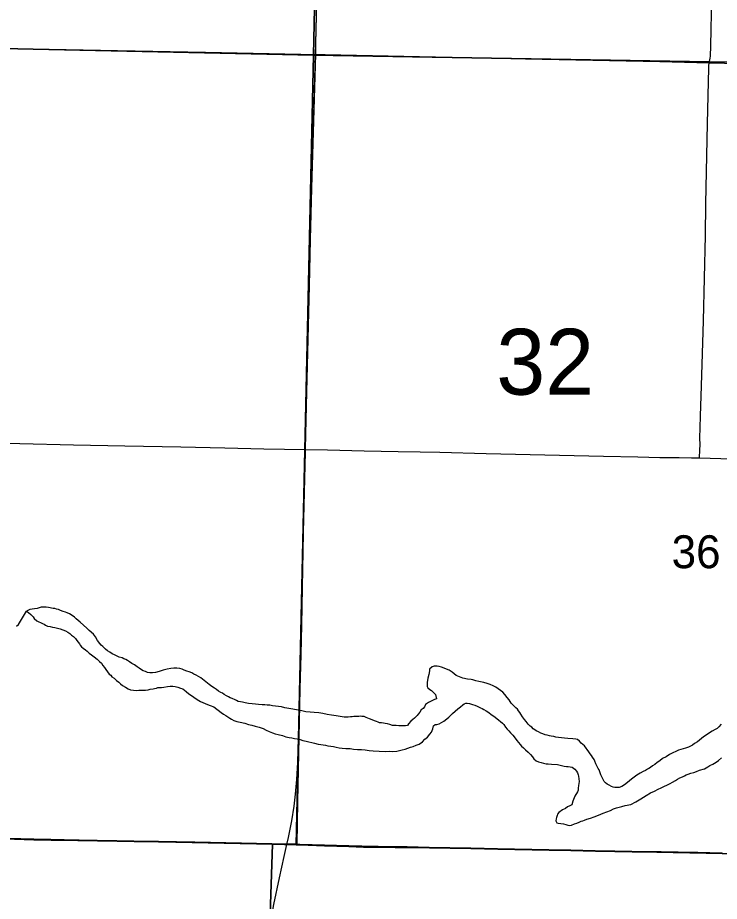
# Model space of a CAD drawing. Extents: x 2.4 to 73.1, y 4.5 to 25.6.
# Drawn here: x 32.789 to 33.235, y 18.547 to 19.109 of the extents above; entities that cross this region are included whole.
import ezdxf

# ---------------------------------------------------------------- set-up
doc = ezdxf.new("R2010")
doc.units = 0
for name, color, linetype in [('GM_X_County_Road', 7, 'Continuous'), ('GM_X_Interchange_Ramps', 7, 'Continuous'), ('GM_X_Major_River', 7, 'Continuous'), ('GM_X_Minor_River', 7, 'Continuous'), ('GM_X_Section', 7, 'Continuous'), ('GM_X_Section_Text', 7, 'Continuous'), ('GM_X_State_Route', 7, 'Continuous'), ('GM_X_Township', 7, 'Continuous'), ('GM_X_Township_Road', 7, 'Continuous')]:
    doc.layers.add(name, color=color, linetype=linetype)

msp = doc.modelspace()

# ---------------------------------------------------------------- linework, layer by layer
at = {"layer": 'GM_X_County_Road'}
for points in [[(33.22907, 19.08006), (33.22948, 19.08189), (33.22967, 19.083), (33.22979, 19.08426), (33.23011, 19.09084), (33.2307, 19.12192)], [(32.47285, 19.09527), (32.47336, 19.09525), (32.51999, 19.09427), (32.53863, 19.09381), (32.55418, 19.09358), (32.63345, 19.09215), (32.70029, 19.09086), (32.72671, 19.09034), (32.74381, 19.0901), (32.77334, 19.0895), (32.78732, 19.08909), (32.8526, 19.08782), (32.90856, 19.08678), (32.96917, 19.08549), (32.97862, 19.08536)], [(32.97862, 19.08536), (32.98472, 19.08527), (33.07486, 19.0834), (33.09351, 19.08306), (33.11215, 19.0826), (33.19765, 19.08101), (33.22907, 19.08006)]]:
    msp.add_lwpolyline(points, dxfattribs=at)
at = {"layer": 'GM_X_Interchange_Ramps'}
msp.add_lwpolyline([(33.23721, 18.57757), (33.22171, 18.578), (33.20931, 18.57828), (33.19844, 18.5785), (33.17982, 18.57874), (33.16895, 18.57888), (33.15653, 18.57913), (33.141, 18.57957), (33.12702, 18.57981), (33.0944, 18.58047), (33.07732, 18.58081), (33.05091, 18.58129), (33.03693, 18.58156), (33.02918, 18.5816), (33.01523, 18.58162), (33.00903, 18.58177), (32.99974, 18.58218), (32.98422, 18.58264), (32.96871, 18.58319), (32.96697, 18.58323), (32.96671, 18.58324), (32.96026, 18.58338), (32.93145, 18.584), (32.90193, 18.58465), (32.87863, 18.58509), (32.86309, 18.58529), (32.85222, 18.58553), (32.82737, 18.58591), (32.81028, 18.58621), (32.79941, 18.58646), (32.77456, 18.58717)], dxfattribs=at)
at = {"layer": 'GM_X_Major_River'}
for points in [[(32.94793, 18.6718), (32.94641, 18.67199), (32.9447, 18.672), (32.94242, 18.67219), (32.94033, 18.67239), (32.93824, 18.67258), (32.93596, 18.67278), (32.93387, 18.67317), (32.93216, 18.67355), (32.93082, 18.67375), (32.92949, 18.67413), (32.92835, 18.6747), (32.92741, 18.67509), (32.92551, 18.67604), (32.92437, 18.67642), (32.92323, 18.677), (32.9219, 18.67757), (32.92057, 18.67853), (32.91943, 18.67929), (32.91829, 18.67986), (32.91696, 18.68063), (32.91563, 18.68158), (32.9143, 18.68254), (32.91259, 18.68349), (32.91088, 18.68483), (32.90575, 18.68902), (32.90423, 18.68998), (32.90271, 18.69074), (32.90119, 18.69151), (32.89987, 18.69227), (32.89834, 18.69284), (32.89682, 18.69342), (32.89511, 18.69399), (32.89378, 18.69457), (32.89226, 18.69495), (32.89036, 18.69515), (32.88846, 18.69515), (32.88656, 18.69497), (32.88428, 18.6946), (32.88161, 18.69403), (32.87914, 18.69309), (32.87686, 18.69253), (32.87496, 18.69234), (32.87325, 18.69235), (32.87173, 18.69254), (32.87039, 18.69311), (32.86906, 18.6935), (32.86736, 18.69464), (32.86641, 18.69522), (32.86508, 18.69617), (32.86356, 18.69732), (32.86185, 18.69827), (32.86033, 18.69923), (32.859, 18.70018), (32.85786, 18.70075), (32.85672, 18.70114), (32.85558, 18.70171), (32.85368, 18.70229), (32.85235, 18.70286), (32.85083, 18.70362), (32.84931, 18.70439), (32.84779, 18.70534), (32.84627, 18.7063), (32.84494, 18.70725), (32.84323, 18.70897), (32.84228, 18.70992), (32.84133, 18.71087), (32.83982, 18.71278), (32.83868, 18.71525), (32.83735, 18.71678), (32.83469, 18.71925), (32.83318, 18.72059), (32.829, 18.7244), (32.82767, 18.72555), (32.82634, 18.72669), (32.8252, 18.72765), (32.82387, 18.72879), (32.82216, 18.72974), (32.82064, 18.73051), (32.8195, 18.73089), (32.81798, 18.73128), (32.81646, 18.73185), (32.81514, 18.73242), (32.8138, 18.73281), (32.81285, 18.73319), (32.81171, 18.73319), (32.81076, 18.73339), (32.80981, 18.73358), (32.80867, 18.73377), (32.80734, 18.73397), (32.8062, 18.73397), (32.80525, 18.73397), (32.80411, 18.73398), (32.80278, 18.7336), (32.80164, 18.73322), (32.79992, 18.73304), (32.7984, 18.73266), (32.79688, 18.73248), (32.79479, 18.73153), (32.79593, 18.73058), (32.79745, 18.72924)], [(32.79745, 18.72924), (32.79896, 18.72791), (32.79972, 18.72677), (32.80124, 18.72524), (32.80257, 18.72467), (32.80371, 18.72428), (32.80485, 18.72371), (32.80599, 18.72314), (32.80694, 18.72256), (32.80808, 18.72199), (32.80979, 18.72161), (32.81131, 18.72122), (32.81283, 18.72103), (32.81454, 18.72064), (32.81625, 18.72026), (32.81796, 18.71968), (32.81948, 18.71892), (32.821, 18.71815), (32.82233, 18.7172), (32.82347, 18.71625), (32.82461, 18.71529), (32.82594, 18.71415), (32.8267, 18.71282), (32.82765, 18.71167), (32.82841, 18.71072), (32.82897, 18.70977), (32.82973, 18.70882), (32.83087, 18.70786), (32.8322, 18.70691), (32.83334, 18.70595), (32.83467, 18.70481), (32.83619, 18.70366), (32.8379, 18.70252), (32.8398, 18.70099), (32.84112, 18.69947), (32.84245, 18.69833), (32.8434, 18.69699), (32.84435, 18.69566), (32.8453, 18.69433), (32.84738, 18.69147), (32.84833, 18.69071), (32.84909, 18.68975), (32.85061, 18.6888), (32.85194, 18.68747), (32.85346, 18.68632), (32.8546, 18.68518), (32.85593, 18.68422), (32.85783, 18.68308), (32.85935, 18.68212), (32.86087, 18.68155), (32.86277, 18.68116), (32.86448, 18.68097), (32.86619, 18.68115), (32.86809, 18.68115), (32.87056, 18.68133), (32.87209, 18.68152), (32.87342, 18.68189), (32.87532, 18.68208), (32.87627, 18.68226), (32.87741, 18.68245), (32.87836, 18.68283), (32.8795, 18.68302), (32.88064, 18.68301), (32.88217, 18.6832), (32.88445, 18.68357), (32.88616, 18.68376), (32.88787, 18.68375), (32.88939, 18.68356), (32.8911, 18.68317), (32.89262, 18.6826), (32.89414, 18.68202), (32.89528, 18.68126), (32.89642, 18.68031), (32.89794, 18.67897), (32.89908, 18.67821), (32.90117, 18.67687), (32.90269, 18.67573), (32.9044, 18.67458), (32.90554, 18.67401), (32.90687, 18.67343), (32.90839, 18.67286), (32.90991, 18.67209), (32.91162, 18.67152), (32.9139, 18.67056), (32.91864, 18.66694), (32.91997, 18.66599), (32.92149, 18.66522), (32.92282, 18.66427), (32.92415, 18.6635), (32.9251, 18.66274), (32.92662, 18.66197), (32.92852, 18.6614), (32.93061, 18.66082), (32.93365, 18.66024), (32.93593, 18.65948), (32.93802, 18.6589), (32.9403, 18.65832), (32.94278, 18.65775), (32.94525, 18.65679), (32.94714, 18.65583), (32.94923, 18.65488)], [(33.10176, 18.67515), (33.10043, 18.67668), (33.09911, 18.67858), (33.09778, 18.67992), (33.09322, 18.68316), (33.09151, 18.68393), (33.0898, 18.68488), (33.08771, 18.68546), (33.08562, 18.68603), (33.08258, 18.6868), (33.08049, 18.68719), (33.07878, 18.68776), (33.07764, 18.68796), (33.07536, 18.68816), (33.07232, 18.68892), (33.06814, 18.69065), (33.06548, 18.69274), (33.06358, 18.69389), (33.06187, 18.69466), (33.06035, 18.69523), (33.05883, 18.6958), (33.05731, 18.69619), (33.05598, 18.69657), (33.05503, 18.69658), (33.05408, 18.69658), (33.05275, 18.69601), (33.05122, 18.6945), (33.05103, 18.69355), (33.05064, 18.69127), (33.05007, 18.6888), (33.04968, 18.68614), (33.04968, 18.68481), (33.04968, 18.68367), (33.05006, 18.68272), (33.05139, 18.68176), (33.05234, 18.681), (33.05405, 18.67928), (33.055, 18.67852), (33.05556, 18.67567), (33.05423, 18.67529), (33.05252, 18.67454), (33.05042, 18.6734), (33.04852, 18.67208), (33.04794, 18.67056), (33.04699, 18.66961), (33.04585, 18.66866), (33.0449, 18.66715), (33.04394, 18.66601), (33.04318, 18.66506), (33.04166, 18.66335), (33.04052, 18.6626), (33.03918, 18.66146), (33.03785, 18.65994), (33.03709, 18.65881), (33.03594, 18.65862), (33.03442, 18.65862), (33.03309, 18.65863), (33.03157, 18.65863), (33.02986, 18.65883), (33.02758, 18.65883), (33.02587, 18.65941), (33.02435, 18.65979), (33.02302, 18.65999), (33.02188, 18.66018), (33.02055, 18.66037), (33.01941, 18.66057), (33.01846, 18.66095), (33.01732, 18.66133), (33.01618, 18.66172), (33.01466, 18.66229), (33.01295, 18.66306), (33.01086, 18.66382), (33.00953, 18.6644), (33.00801, 18.66459), (33.00706, 18.66478), (33.0061, 18.6646), (33.00306, 18.66442), (33.00192, 18.66423), (33.00078, 18.66423), (32.99945, 18.66405), (32.99679, 18.66405), (32.99432, 18.66444), (32.99165, 18.66502), (32.9888, 18.66541), (32.98595, 18.66579), (32.98329, 18.66637), (32.98063, 18.66676), (32.97778, 18.66696), (32.97512, 18.66735), (32.97245, 18.66754), (32.96998, 18.66812), (32.96751, 18.66851), (32.96428, 18.66909), (32.96162, 18.66948), (32.95915, 18.67005), (32.95687, 18.67063), (32.95497, 18.67083), (32.95307, 18.67102), (32.95117, 18.67122), (32.94965, 18.6716), (32.94793, 18.6718)], [(33.23655, 18.65956), (33.23521, 18.65785), (33.23407, 18.6569), (33.23293, 18.65615), (33.23102, 18.6552), (33.2255, 18.65161), (33.2215, 18.64839), (33.21979, 18.64725), (33.21846, 18.64631), (33.21579, 18.64498), (33.21389, 18.64442), (33.20952, 18.6431), (33.2078, 18.64235), (33.2059, 18.6414), (33.20381, 18.64027), (33.20171, 18.63894), (33.19924, 18.63781), (33.19771, 18.63629), (33.196, 18.63516), (33.19448, 18.63402), (33.19296, 18.63308), (33.19162, 18.63213), (33.19067, 18.63137), (33.18972, 18.631), (33.18858, 18.63024), (33.18705, 18.62948), (33.18515, 18.62854), (33.18306, 18.62721), (33.17963, 18.62456), (33.17716, 18.62248), (33.17506, 18.62097), (33.17354, 18.62002), (33.17183, 18.61945), (33.16992, 18.61946), (33.16897, 18.61946), (33.16802, 18.61966), (33.16688, 18.62004), (33.16536, 18.6208), (33.16403, 18.62138), (33.16308, 18.62233), (33.16233, 18.62328), (33.16138, 18.62481), (33.16062, 18.62652), (33.16005, 18.62747), (33.15967, 18.62861), (33.15911, 18.63051), (33.15835, 18.63147), (33.15778, 18.6328), (33.15683, 18.63432), (33.15626, 18.63603), (33.15589, 18.63718), (33.15475, 18.6387), (33.15418, 18.63965), (33.15342, 18.64079), (33.15247, 18.64194), (33.14963, 18.64575), (33.14868, 18.6467), (33.14754, 18.64765), (33.14659, 18.6488), (33.14526, 18.64994), (33.14412, 18.65013), (33.14222, 18.65033), (33.13918, 18.65053), (33.1369, 18.65073), (33.135, 18.65092), (33.13309, 18.65112), (33.13157, 18.65131), (33.13024, 18.6517), (33.12853, 18.65189), (33.12739, 18.65227), (33.12606, 18.65266), (33.12473, 18.65285), (33.12321, 18.65343), (33.12188, 18.654), (33.12036, 18.65476), (33.11903, 18.65534), (33.11808, 18.6561), (33.11713, 18.65667), (33.11618, 18.65763), (33.11523, 18.65839), (33.11391, 18.65972), (33.11258, 18.66125), (33.11163, 18.66258), (33.1103, 18.6643), (33.10916, 18.66601), (33.10859, 18.66696), (33.10783, 18.66811), (33.10708, 18.66906), (33.10613, 18.67001), (33.1048, 18.67134), (33.10309, 18.67306), (33.10176, 18.67515)], [(32.94923, 18.65488), (32.95114, 18.65411), (32.95303, 18.65354), (32.95494, 18.65296), (32.9576, 18.65238), (32.95969, 18.65162), (32.96178, 18.65123), (32.96349, 18.65084), (32.9652, 18.65046), (32.96691, 18.65027), (32.96881, 18.64988), (32.97052, 18.6493), (32.97261, 18.64892), (32.97432, 18.64834), (32.97622, 18.64796), (32.97793, 18.64757), (32.98021, 18.647), (32.98192, 18.64661), (32.98344, 18.64642), (32.98497, 18.64622), (32.98649, 18.64584), (32.98839, 18.64564), (32.9901, 18.64545), (32.99181, 18.64506), (32.99371, 18.64468), (32.99561, 18.64429), (32.99789, 18.64409), (33.00074, 18.64409), (33.00283, 18.6437), (33.00531, 18.6435), (33.00778, 18.64349), (33.01025, 18.6433), (33.01272, 18.64291), (33.01519, 18.64271), (33.02299, 18.64231), (33.02546, 18.64249), (33.02774, 18.6423), (33.0304, 18.64248), (33.03211, 18.64286), (33.03383, 18.64323), (33.03573, 18.64379), (33.03725, 18.64436), (33.03896, 18.64493), (33.04067, 18.64549), (33.04258, 18.64625), (33.04448, 18.647), (33.04657, 18.64833), (33.0481, 18.65003), (33.04981, 18.65136), (33.05134, 18.65325), (33.05248, 18.65458), (33.05324, 18.65667), (33.05363, 18.65857), (33.05477, 18.65932), (33.05572, 18.65951), (33.05724, 18.65989), (33.05877, 18.66064), (33.06029, 18.66159), (33.06219, 18.66291), (33.06333, 18.66405), (33.06448, 18.66519), (33.06581, 18.66633), (33.06753, 18.66784), (33.06924, 18.66936), (33.07076, 18.67068), (33.07229, 18.67182), (33.07324, 18.67258), (33.07419, 18.67295), (33.07514, 18.67295), (33.07666, 18.67276), (33.07837, 18.67218), (33.07989, 18.67161), (33.08141, 18.67103), (33.0835, 18.67007), (33.08464, 18.66969), (33.08578, 18.66893), (33.08711, 18.66816), (33.08882, 18.66702), (33.09034, 18.66587), (33.09205, 18.66473), (33.09395, 18.6632), (33.09755, 18.66034), (33.0985, 18.65939), (33.09945, 18.65768), (33.10059, 18.65634), (33.10154, 18.65539), (33.10268, 18.65406), (33.10419, 18.65272), (33.10552, 18.65063), (33.10666, 18.64929), (33.1078, 18.64796), (33.10875, 18.64663), (33.1097, 18.64567), (33.11083, 18.64453), (33.11216, 18.64338), (33.11387, 18.64186), (33.11539, 18.64033), (33.11672, 18.63881), (33.11748, 18.63748), (33.119, 18.63633), (33.12052, 18.63576)], [(33.12052, 18.63576), (33.12223, 18.63518), (33.12356, 18.6348), (33.12527, 18.63441), (33.1266, 18.63441), (33.12869, 18.63421), (33.13249, 18.63401), (33.13515, 18.63343), (33.13686, 18.63286), (33.13819, 18.63267), (33.13933, 18.63266), (33.14067, 18.63247), (33.14181, 18.63228), (33.14351, 18.63094), (33.14465, 18.6298), (33.14522, 18.62865), (33.14579, 18.62751), (33.14598, 18.62656), (33.14635, 18.62314), (33.14616, 18.622), (33.14597, 18.62067), (33.14578, 18.61896), (33.14577, 18.61763), (33.1452, 18.61668), (33.14367, 18.61383), (33.14234, 18.61061), (33.14157, 18.60833), (33.14043, 18.60776), (33.13891, 18.60701), (33.13758, 18.60606), (33.13567, 18.60511), (33.13339, 18.60341), (33.13263, 18.60246), (33.13225, 18.60151), (33.13186, 18.60037), (33.13167, 18.59942), (33.13148, 18.59809), (33.13205, 18.59695), (33.133, 18.59676), (33.13471, 18.59656), (33.13642, 18.59618), (33.13794, 18.59579), (33.13908, 18.59541), (33.14022, 18.59522), (33.14155, 18.5954), (33.14326, 18.59616), (33.14479, 18.59673), (33.14631, 18.59729), (33.14764, 18.59786), (33.14859, 18.59824), (33.14973, 18.59861), (33.15125, 18.59918), (33.15354, 18.59993), (33.15582, 18.60068), (33.15867, 18.60182), (33.16153, 18.60295), (33.164, 18.60389), (33.16629, 18.60484), (33.16819, 18.60578), (33.17009, 18.60634), (33.1718, 18.60691), (33.17351, 18.60729), (33.17561, 18.60785), (33.17922, 18.6086), (33.18227, 18.6103), (33.1855, 18.61219), (33.18893, 18.61427), (33.19178, 18.61597), (33.19426, 18.61711), (33.19654, 18.61824), (33.19845, 18.61919), (33.20415, 18.62183), (33.20568, 18.62278), (33.20758, 18.62391), (33.20891, 18.62467), (33.21044, 18.62561), (33.21196, 18.62618), (33.21329, 18.62675), (33.21443, 18.62731), (33.21576, 18.62788), (33.21728, 18.62845), (33.21919, 18.62882), (33.2209, 18.62957), (33.2228, 18.63033), (33.22604, 18.63127), (33.22813, 18.63259), (33.22946, 18.63335), (33.23137, 18.6343), (33.23232, 18.63486), (33.23346, 18.63543), (33.23498, 18.63657), (33.23689, 18.63827)]]:
    msp.add_lwpolyline(points, dxfattribs=at)
at = {"layer": 'GM_X_Minor_River'}
msp.add_lwpolyline([(32.78831, 18.72186), (32.78964, 18.72299), (32.79479, 18.73153)], dxfattribs=at)
at = {"layer": 'GM_X_Section'}
for points in [[(32.98811, 19.59151), (32.97722, 19.08485), (32.47209, 19.0957), (32.48193, 19.59785)], [(33.49557, 19.58326), (33.48089, 19.0765), (32.97722, 19.08485), (32.98811, 19.59151)], [(32.97722, 19.08485), (32.96625, 18.58294), (32.95129, 18.58326), (32.4596, 18.59343), (32.47209, 19.0957)], [(32.97722, 19.08485), (33.48089, 19.0765), (33.46684, 18.57275), (32.96625, 18.58294)], [(32.4596, 18.59343), (32.95129, 18.58326), (32.93411, 18.06556), (32.43473, 18.07911), (32.4452, 18.59355)], [(32.95129, 18.58326), (32.96625, 18.58294), (33.46684, 18.57275), (33.45592, 18.07311), (33.45507, 18.05115), (32.93411, 18.06556)]]:
    msp.add_lwpolyline(points, close=True, dxfattribs=at)
at = {"layer": 'GM_X_State_Route'}
for points in [[(32.97862, 19.08536), (32.9788, 19.09205), (32.98002, 19.14643), (32.98085, 19.19771), (32.98195, 19.24744), (32.98296, 19.30338), (32.98311, 19.31581), (32.98323, 19.33756), (32.98394, 19.37486), (32.98428, 19.3904), (32.98452, 19.40127), (32.98504, 19.41991), (32.98561, 19.43854), (32.98595, 19.44786), (32.98649, 19.47116), (32.98718, 19.50534), (32.98801, 19.55818), (32.98866, 19.59177)], [(32.96954, 18.71319), (32.96976, 18.72225), (32.97048, 18.75799), (32.97087, 18.7813), (32.97203, 18.83258), (32.97208, 18.83424), (32.97255, 18.85278), (32.97327, 18.87919), (32.97476, 18.93823), (32.97542, 18.96776), (32.97626, 19.00038), (32.97862, 19.08536)], [(32.96038, 18.5831), (32.96139, 18.5876), (32.96345, 18.59827), (32.96495, 18.60746), (32.96594, 18.61515), (32.96679, 18.62442), (32.96739, 18.63526), (32.96868, 18.68186), (32.96931, 18.70362), (32.96954, 18.71319)], [(32.94768, 18.49463), (32.94816, 18.50953), (32.94874, 18.5204), (32.94944, 18.52816), (32.95049, 18.53588), (32.9521, 18.54508), (32.9556, 18.56183), (32.95864, 18.57549), (32.96038, 18.5831)]]:
    msp.add_lwpolyline(points, dxfattribs=at)
at = {"layer": 'GM_X_Township'}
msp.add_lwpolyline([(32.9799, 19.14671), (32.97868, 19.09233), (32.9785, 19.08563), (32.97615, 19.00066), (32.9753, 18.96803), (32.97465, 18.93851), (32.97315, 18.87946), (32.97243, 18.85305), (32.97196, 18.83452), (32.97192, 18.83285), (32.97076, 18.78158), (32.97036, 18.75826), (32.96965, 18.72253), (32.96919, 18.70389), (32.96856, 18.68214), (32.96707, 18.61018), (32.96671, 18.58324), (32.96026, 18.58338), (32.93145, 18.584), (32.90193, 18.58465), (32.87863, 18.58509), (32.86309, 18.58529), (32.85222, 18.58553), (32.82737, 18.58591), (32.81028, 18.58621), (32.79941, 18.58646), (32.77456, 18.58717)], dxfattribs=at)
at = {"layer": 'GM_X_Township_Road'}
for points in [[(32.47285, 19.09527), (32.47336, 19.09525), (32.51999, 19.09427), (32.53863, 19.09381), (32.55418, 19.09358), (32.63345, 19.09215), (32.70029, 19.09086), (32.72671, 19.09034), (32.74381, 19.0901), (32.77334, 19.0895), (32.78732, 19.08909), (32.8526, 19.08782), (32.90856, 19.08678), (32.96917, 19.08549), (32.97862, 19.08536)], [(32.97862, 19.08536), (32.98472, 19.08527), (33.07486, 19.0834), (33.09351, 19.08306), (33.11215, 19.0826), (33.19765, 19.08101), (33.22907, 19.08006)], [(33.22292, 18.82885), (33.2231, 18.83402), (33.22321, 18.83711), (33.22318, 18.84176), (33.22333, 18.84794), (33.22361, 18.85567), (33.22397, 18.86806), (33.22466, 18.88819), (33.22536, 18.91608), (33.22665, 18.97031), (33.22696, 18.99046), (33.22788, 19.04159), (33.22849, 19.06793), (33.2287, 19.07676), (33.22878, 19.07826), (33.22907, 19.08006)], [(33.22907, 19.08006), (33.25819, 19.07944), (33.29857, 19.07878), (33.31565, 19.07839), (33.33584, 19.07798), (33.37, 19.07726), (33.42435, 19.07624), (33.46939, 19.07532), (33.48958, 19.07495), (33.49322, 19.07488)], [(32.46675, 18.84469), (32.47963, 18.84463), (32.50294, 18.84401), (32.53558, 18.84351), (32.58064, 18.84251), (32.6226, 18.84163), (32.65368, 18.8412), (32.66766, 18.8409), (32.71273, 18.83986), (32.73293, 18.8395), (32.764, 18.83869), (32.79042, 18.83806), (32.8246, 18.83722), (32.85723, 18.83663), (32.89298, 18.83587), (32.92095, 18.83539), (32.94581, 18.83473), (32.97208, 18.83424)], [(32.97208, 18.83424), (32.98621, 18.83398), (33.00952, 18.83341), (33.03128, 18.83295), (33.04526, 18.83267), (33.05769, 18.83249), (33.08722, 18.83178), (33.12451, 18.83094), (33.16181, 18.83002), (33.18356, 18.82954), (33.19753, 18.82924), (33.20996, 18.82915), (33.21773, 18.829), (33.22292, 18.82885)], [(33.22292, 18.82885), (33.23637, 18.82846), (33.25657, 18.82809), (33.27988, 18.82754), (33.30132, 18.82728), (33.30758, 18.82718), (33.32788, 18.82703), (33.33667, 18.82699), (33.38677, 18.82655), (33.40205, 18.8265), (33.42073, 18.8262), (33.44249, 18.82579), (33.46032, 18.82538), (33.47497, 18.82518), (33.47964, 18.82518), (33.48282, 18.8254), (33.48515, 18.82565), (33.48708, 18.8259), (33.48963, 18.82639)], [(32.71514, 18.58827), (32.71566, 18.58827), (32.74051, 18.58785), (32.77468, 18.58689), (32.79953, 18.58619), (32.8104, 18.58594), (32.82749, 18.58563), (32.85234, 18.58525), (32.86321, 18.58501), (32.87875, 18.58482), (32.90205, 18.58438), (32.93157, 18.58372), (32.96038, 18.5831)], [(32.96038, 18.5831), (32.96683, 18.58296), (32.96883, 18.58292), (32.98434, 18.58236), (32.99985, 18.58191), (33.00915, 18.5815), (33.01535, 18.58134), (33.0293, 18.58132), (33.03705, 18.58129), (33.05102, 18.58101), (33.07743, 18.58054), (33.09452, 18.5802), (33.12714, 18.57953), (33.14112, 18.57929), (33.15665, 18.57885), (33.16907, 18.57861), (33.17994, 18.57846), (33.19856, 18.57822), (33.20943, 18.578), (33.21687, 18.57784)], [(33.21687, 18.57784), (33.22183, 18.57773), (33.23733, 18.5773), (33.25442, 18.57705), (33.26218, 18.57702), (33.27151, 18.57683), (33.2917, 18.5764), (33.31966, 18.57569), (33.34451, 18.57525), (33.3616, 18.575), (33.38335, 18.57457), (33.42996, 18.57361), (33.46569, 18.57292), (33.46899, 18.57284)]]:
    msp.add_lwpolyline(points, dxfattribs=at)

# ---------------------------------------------------------------- texts
at = {"layer": 'GM_X_Section_Text'}
for s, height, p in [('32', 0.041856, (33.09361, 18.8691)), ('36', 0.020928, (33.20514, 18.75877))]:
    msp.add_text(s, height=height, rotation=0, dxfattribs=at).set_placement(p)

doc.saveas('drawing.dxf')
